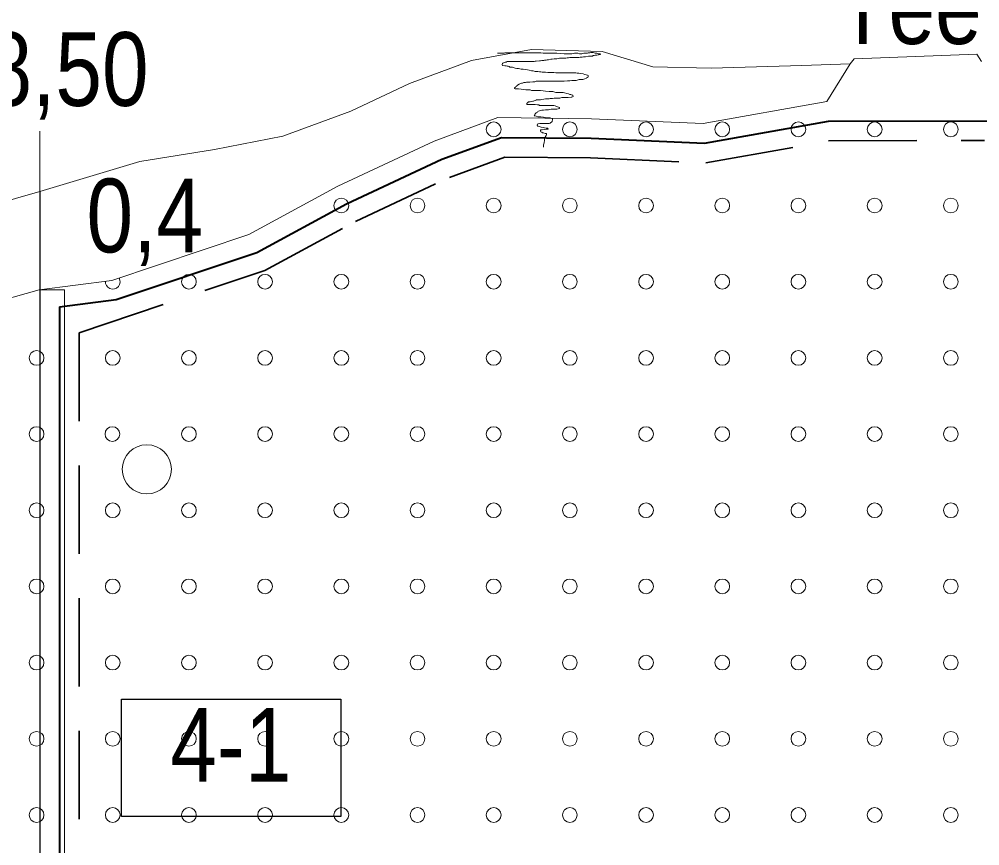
# Model space of a CAD drawing. Extents: x 640121 to 640955, y 6441885 to 6442246.
# Drawn here: x 640648.85 to 640687.94, y 6442170.54 to 6442204.18 of the extents above; entities that cross this region are included whole.
import ezdxf
from ezdxf.enums import TextEntityAlignment as Align

# ---------------------------------------------------------------- set-up
doc = ezdxf.new("R2010")
doc.units = 0
doc.header["$LTSCALE"] = 1.2
doc.linetypes.add('MEDIUM_DASHED', pattern=[4.5, 3, -1.5])
for name, color, linetype, lineweight in [('31', 7, 'Continuous', 13), ('32', 7, 'Continuous', 13), ('33', 7, 'Continuous', 13), ('35', 7, 'Continuous', 35), ('40', 7, 'Continuous', 13), ('43', 7, 'Continuous', 13), ('47', 7, 'Continuous', 13)]:
    doc.layers.add(name, color=color, linetype=linetype, lineweight=lineweight)

msp = doc.modelspace()

# ---------------------------------------------------------------- linework, layer by layer
at = {"layer": '31'}
for points in [[(640635.03, 6442189.74), (640635.65, 6442190.39), (640637.35, 6442192.02), (640639.06, 6442193.19), (640642.55, 6442194.82), (640644.42, 6442195.55), (640646.61, 6442196.28), (640649.69, 6442197.16), (640653.76, 6442198.39), (640656.8, 6442198.87), (640659.58, 6442199.42), (640662.34, 6442200.43), (640664.73, 6442201.56), (640667.25, 6442202.5), (640669.69, 6442202.94), (640672.57, 6442202.86), (640674.63, 6442202.24), (640677.01, 6442202.19), (640680.69, 6442202.29), (640682.66, 6442202.36), (640682.82, 6442202.57), (640687.82, 6442202.76), (640688.01, 6442202.46)], [(640635.03, 6442184.5), (640638.16, 6442187.48), (640641.08, 6442189.5), (640643.27, 6442190.84), (640646.48, 6442192.27), (640649.66, 6442193.16), (640652.62, 6442193.55), (640658.2, 6442195.42), (640661.81, 6442197.38), (640665.74, 6442199.21), (640668.33, 6442200.18), (640672.14, 6442200.13), (640676.68, 6442199.93), (640681.71, 6442200.83), (640682.66, 6442202.36)]]:
    msp.add_lwpolyline(points, dxfattribs=at)
at = {"layer": '32', "lineweight": 25}
msp.add_line((640649.69, 6442197.16), (640649.69, 6442075.16), dxfattribs=at)
at = {"layer": '33'}
msp.add_lwpolyline([(640650.69, 6442157.16), (640650.69, 6442193.16), (640649.69, 6442193.16), (640649.69, 6442193.16), (640649.69, 6442157.16)], close=True, dxfattribs=at)
at = {"layer": '33', "lineweight": 25}
msp.add_lwpolyline([(640653.02, 6442176.51), (640661.94, 6442176.51), (640661.94, 6442171.73), (640653.02, 6442171.73)], close=True, dxfattribs=at)
at = {"layer": '35', "lineweight": 40}
for p, q in [((640681.78, 6442200.03), (640688.53, 6442200.04)), ((640650.49, 6442192.47), (640650.49, 6442078.2))]:
    msp.add_line(p, q, dxfattribs=at)
at = {"layer": '35', "lineweight": 13}
msp.add_line((640649.69, 6442197.16), (640649.69, 6442199.62), dxfattribs=at)
at = {"layer": '35', "linetype": 'MEDIUM_DASHED'}
for p, q in [((640681.78, 6442199.23), (640688.13, 6442199.24)), ((640651.29, 6442191.42), (640651.29, 6442127.97))]:
    msp.add_line(p, q, dxfattribs=at)
at = {"layer": '35', "lineweight": 40}
msp.add_lwpolyline([(640650.49, 6442192.47), (640652.8, 6442192.77), (640658.52, 6442194.69), (640662.17, 6442196.67), (640666.05, 6442198.48), (640668.47, 6442199.37), (640672.12, 6442199.33), (640676.73, 6442199.13), (640681.78, 6442200.03)], dxfattribs=at)
at = {"layer": '35', "linetype": 'MEDIUM_DASHED'}
msp.add_lwpolyline([(640651.29, 6442191.42), (640658.84, 6442193.95), (640662.53, 6442195.95), (640666.36, 6442197.74), (640668.61, 6442198.57), (640672.1, 6442198.54), (640676.79, 6442198.33), (640681.92, 6442199.24)], dxfattribs=at)
at = {"layer": '40'}
for points in [[(640668.31, 6442202.8), (640668.37, 6442202.8), (640668.47, 6442202.8), (640668.58, 6442202.8), (640668.61, 6442202.81), (640668.71, 6442202.81), (640668.87, 6442202.81), (640669.19, 6442202.81), (640669.37, 6442202.81), (640669.41, 6442202.81), (640669.45, 6442202.81), (640669.52, 6442202.81), (640669.6, 6442202.81), (640669.71, 6442202.81), (640669.79, 6442202.81), (640669.85, 6442202.81), (640669.94, 6442202.81), (640670.01, 6442202.81), (640670.08, 6442202.81), (640670.17, 6442202.8), (640670.21, 6442202.8), (640670.29, 6442202.8), (640670.38, 6442202.8), (640670.72, 6442202.79), (640671.03, 6442202.77), (640671.13, 6442202.77), (640671.19, 6442202.77), (640671.22, 6442202.77), (640671.27, 6442202.77), (640671.34, 6442202.77), (640671.44, 6442202.79), (640671.49, 6442202.79), (640671.52, 6442202.79), (640671.55, 6442202.79), (640671.58, 6442202.79), (640671.65, 6442202.77), (640671.69, 6442202.77), (640671.74, 6442202.77), (640671.83, 6442202.79), (640671.89, 6442202.79), (640671.97, 6442202.8), (640672, 6442202.81), (640672.07, 6442202.81), (640672.11, 6442202.82), (640672.16, 6442202.82), (640672.21, 6442202.82), (640672.24, 6442202.81), (640672.28, 6442202.8), (640672.33, 6442202.79), (640672.36, 6442202.79)], [(640672.36, 6442202.79), (640672.41, 6442202.77), (640672.45, 6442202.77), (640672.49, 6442202.77), (640672.52, 6442202.75), (640672.49, 6442202.74), (640672.51, 6442202.75), (640672.47, 6442202.74), (640672.42, 6442202.73), (640672.36, 6442202.71), (640672.33, 6442202.71), (640672.28, 6442202.71), (640672.24, 6442202.7), (640672.21, 6442202.7), (640672.18, 6442202.68), (640672.12, 6442202.68), (640672.05, 6442202.67), (640672.01, 6442202.67), (640671.89, 6442202.65), (640671.85, 6442202.64), (640671.81, 6442202.64), (640671.76, 6442202.63), (640671.71, 6442202.63), (640671.68, 6442202.63), (640671.62, 6442202.62), (640671.58, 6442202.62), (640671.47, 6442202.62), (640671.41, 6442202.62), (640671.34, 6442202.62), (640671.26, 6442202.62), (640671.2, 6442202.61), (640671.15, 6442202.61), (640671.09, 6442202.59), (640671.03, 6442202.59), (640670.86, 6442202.59), (640670.83, 6442202.59), (640670.79, 6442202.58), (640670.72, 6442202.57), (640670.62, 6442202.56), (640670.54, 6442202.55), (640670.48, 6442202.55), (640670.39, 6442202.53), (640670.33, 6442202.53), (640670.29, 6442202.51), (640670.23, 6442202.51), (640670.2, 6442202.5), (640670.17, 6442202.5), (640670.11, 6442202.5), (640670.06, 6442202.49), (640670.02, 6442202.49), (640669.89, 6442202.47), (640669.84, 6442202.47)], [(640669.84, 6442202.47), (640669.81, 6442202.46), (640669.75, 6442202.46), (640669.71, 6442202.45), (640669.67, 6442202.45), (640669.64, 6442202.45), (640669.59, 6442202.45), (640669.54, 6442202.45), (640669.49, 6442202.45), (640669.42, 6442202.45), (640669.39, 6442202.45), (640669.33, 6442202.46), (640669.29, 6442202.46), (640669.25, 6442202.46), (640669.22, 6442202.46), (640669.17, 6442202.46), (640669.12, 6442202.46), (640669.05, 6442202.46), (640669.01, 6442202.46), (640668.98, 6442202.46), (640668.92, 6442202.46), (640668.88, 6442202.46), (640668.83, 6442202.46), (640668.8, 6442202.46), (640668.75, 6442202.46), (640668.7, 6442202.45), (640668.67, 6442202.43), (640668.62, 6442202.43), (640668.58, 6442202.41), (640668.56, 6442202.4), (640668.53, 6442202.39), (640668.51, 6442202.37), (640668.5, 6442202.33), (640668.51, 6442202.29), (640668.61, 6442202.28), (640668.67, 6442202.28), (640668.7, 6442202.26), (640668.75, 6442202.26), (640668.79, 6442202.25), (640668.81, 6442202.23), (640668.87, 6442202.23), (640668.92, 6442202.22), (640668.95, 6442202.21), (640669.03, 6442202.19), (640669.1, 6442202.17), (640669.17, 6442202.17), (640669.22, 6442202.16), (640669.27, 6442202.15), (640669.35, 6442202.14), (640669.46, 6442202.13)], [(640669.46, 6442202.13), (640669.6, 6442202.1), (640669.7, 6442202.08), (640669.76, 6442202.07), (640669.85, 6442202.05), (640669.95, 6442202.05), (640670.02, 6442202.04), (640670.08, 6442202.04), (640670.13, 6442202.02), (640670.21, 6442202.02), (640670.27, 6442202.02), (640670.36, 6442202.01), (640670.44, 6442202.01), (640670.51, 6442202.01), (640670.61, 6442202.01), (640670.69, 6442201.99), (640670.75, 6442201.99), (640670.79, 6442201.99), (640670.86, 6442201.99), (640670.93, 6442201.99), (640671.02, 6442201.99), (640671.11, 6442201.99), (640671.2, 6442201.99), (640671.26, 6442201.99), (640671.34, 6442201.99), (640671.38, 6442201.99), (640671.44, 6442201.99), (640671.5, 6442201.99), (640671.56, 6442201.98), (640671.62, 6442201.98), (640671.67, 6442201.97), (640671.8, 6442201.96), (640671.86, 6442201.93), (640671.92, 6442201.91), (640671.97, 6442201.9), (640672, 6442201.89), (640672, 6442201.85), (640671.99, 6442201.81), (640671.97, 6442201.8), (640671.94, 6442201.79), (640671.92, 6442201.77), (640671.87, 6442201.75), (640671.79, 6442201.73), (640671.64, 6442201.72), (640671.51, 6442201.69), (640671.44, 6442201.68), (640671.34, 6442201.68), (640671.26, 6442201.67), (640671.16, 6442201.67), (640671.03, 6442201.66), (640670.84, 6442201.66), (640670.67, 6442201.66)], [(640670.67, 6442201.66), (640670.59, 6442201.66), (640670.51, 6442201.66), (640670.43, 6442201.66), (640670.37, 6442201.66), (640670.31, 6442201.66), (640670.23, 6442201.66), (640670.14, 6442201.65), (640669.96, 6442201.65), (640669.88, 6442201.65), (640669.83, 6442201.63), (640669.75, 6442201.63), (640669.63, 6442201.61), (640669.49, 6442201.61), (640669.45, 6442201.6), (640669.39, 6442201.6), (640669.36, 6442201.59), (640669.33, 6442201.57), (640669.29, 6442201.57), (640669.25, 6442201.56), (640669.22, 6442201.55), (640669.19, 6442201.53), (640669.13, 6442201.49), (640669.1, 6442201.47), (640669.09, 6442201.44), (640669.05, 6442201.43), (640669.04, 6442201.41), (640669.01, 6442201.38), (640669, 6442201.36), (640669.03, 6442201.35), (640669.06, 6442201.35), (640669.12, 6442201.35), (640669.17, 6442201.35), (640669.28, 6442201.33), (640669.36, 6442201.32), (640669.46, 6442201.31), (640669.58, 6442201.3), (640669.64, 6442201.3), (640669.7, 6442201.27), (640669.76, 6442201.27), (640669.93, 6442201.27), (640670.06, 6442201.27), (640670.17, 6442201.26), (640670.27, 6442201.25), (640670.42, 6442201.24), (640670.56, 6442201.24), (640670.68, 6442201.2), (640670.77, 6442201.2), (640670.86, 6442201.2), (640670.95, 6442201.19)], [(640670.95, 6442201.19), (640670.99, 6442201.19), (640671.04, 6442201.18), (640671.13, 6442201.15), (640671.2, 6442201.14), (640671.25, 6442201.12), (640671.29, 6442201.11), (640671.35, 6442201.09), (640671.38, 6442201.08), (640671.39, 6442201.03), (640671.37, 6442201.02), (640671.34, 6442201.01), (640671.31, 6442201), (640671.19, 6442200.99), (640671.13, 6442200.99), (640671.09, 6442200.99), (640671.02, 6442200.99), (640670.93, 6442200.99), (640670.85, 6442200.97), (640670.8, 6442200.97), (640670.75, 6442200.97), (640670.62, 6442200.97), (640670.55, 6442200.95), (640670.51, 6442200.95), (640670.45, 6442200.95), (640670.42, 6442200.94), (640670.36, 6442200.94), (640670.27, 6442200.94), (640670.2, 6442200.93), (640670.12, 6442200.91), (640670.06, 6442200.9), (640670.02, 6442200.9), (640669.97, 6442200.9), (640669.94, 6442200.89), (640669.88, 6442200.89), (640669.87, 6442200.87), (640669.81, 6442200.85), (640669.78, 6442200.84), (640669.75, 6442200.84), (640669.7, 6442200.83), (640669.64, 6442200.82), (640669.58, 6442200.81), (640669.53, 6442200.78), (640669.51, 6442200.76), (640669.51, 6442200.71), (640669.54, 6442200.71), (640669.61, 6442200.71), (640669.71, 6442200.7), (640669.79, 6442200.7), (640669.84, 6442200.7), (640669.94, 6442200.69), (640670, 6442200.69)], [(640670, 6442200.69), (640670.02, 6442200.67), (640670.06, 6442200.67), (640670.12, 6442200.67), (640670.19, 6442200.67), (640670.23, 6442200.67), (640670.33, 6442200.66), (640670.42, 6442200.66), (640670.45, 6442200.66), (640670.5, 6442200.66), (640670.54, 6442200.66), (640670.6, 6442200.66), (640670.66, 6442200.65), (640670.71, 6442200.63), (640670.75, 6442200.61), (640670.8, 6442200.6), (640670.84, 6442200.59), (640670.84, 6442200.54), (640670.72, 6442200.52), (640670.56, 6442200.51), (640670.5, 6442200.51), (640670.39, 6442200.49), (640670.33, 6442200.49), (640670.26, 6442200.49), (640670.19, 6442200.48), (640670.12, 6442200.48), (640670.05, 6442200.46), (640669.96, 6442200.42), (640669.94, 6442200.4), (640669.89, 6442200.37), (640669.87, 6442200.35), (640669.84, 6442200.33), (640669.83, 6442200.29), (640669.81, 6442200.25), (640669.83, 6442200.24), (640669.88, 6442200.23), (640669.95, 6442200.21), (640670.08, 6442200.21), (640670.19, 6442200.19), (640670.25, 6442200.18), (640670.3, 6442200.17), (640670.37, 6442200.17), (640670.45, 6442200.16), (640670.55, 6442200.12), (640670.55, 6442200.07), (640670.54, 6442200.04), (640670.53, 6442200.01), (640670.45, 6442199.95), (640670.42, 6442199.94), (640670.36, 6442199.94), (640670.27, 6442199.94), (640670.19, 6442199.94), (640670.12, 6442199.94), (640670.03, 6442199.94), (640669.95, 6442199.92), (640669.94, 6442199.88), (640669.93, 6442199.86), (640669.94, 6442199.83), (640669.97, 6442199.82), (640670.09, 6442199.79), (640670.18, 6442199.77), (640670.23, 6442199.76), (640670.29, 6442199.75), (640670.35, 6442199.74), (640670.38, 6442199.71), (640670.36, 6442199.7), (640670.3, 6442199.7), (640670.23, 6442199.69), (640670.13, 6442199.68), (640670.09, 6442199.68), (640670.06, 6442199.67), (640670.06, 6442199.62), (640670.08, 6442199.59), (640670.11, 6442199.58), (640670.14, 6442199.56), (640670.19, 6442199.55), (640670.25, 6442199.53), (640670.3, 6442199.52), (640670.31, 6442199.47), (640670.29, 6442199.45), (640670.27, 6442199.41), (640670.25, 6442199.38), (640670.23, 6442199.35), (640670.23, 6442199.31), (640670.23, 6442199.26), (640670.23, 6442199.22), (640670.21, 6442199.19), (640670.21, 6442199.14), (640670.2, 6442199.11), (640670.19, 6442199.07), (640670.18, 6442199.03), (640670.18, 6442198.98), (640670.18, 6442198.97), (640670.18, 6442199.01)]]:
    msp.add_lwpolyline(points, dxfattribs=at)
at = {"layer": '43'}
for centre in [(640668.157, 6442199.695), (640671.257, 6442199.695), (640674.357, 6442199.695), (640677.457, 6442199.695), (640680.557, 6442199.695), (640683.657, 6442199.695), (640686.757, 6442199.695), (640661.957, 6442196.595), (640665.057, 6442196.595), (640668.157, 6442196.595), (640671.257, 6442196.595), (640674.357, 6442196.595), (640677.457, 6442196.595), (640680.557, 6442196.595), (640683.657, 6442196.595), (640686.757, 6442196.595), (640655.757, 6442193.495), (640658.857, 6442193.495), (640661.957, 6442193.495), (640665.057, 6442193.495), (640668.157, 6442193.495), (640671.257, 6442193.495), (640674.357, 6442193.495), (640677.457, 6442193.495), (640680.557, 6442193.495), (640683.657, 6442193.495), (640686.757, 6442193.495), (640649.557, 6442190.395), (640652.657, 6442190.395), (640655.757, 6442190.395), (640658.857, 6442190.395), (640661.957, 6442190.395), (640665.057, 6442190.395), (640668.157, 6442190.395), (640671.257, 6442190.395), (640674.357, 6442190.395), (640677.457, 6442190.395), (640680.557, 6442190.395), (640683.657, 6442190.395), (640686.757, 6442190.395), (640649.557, 6442187.295), (640652.643, 6442187.295), (640655.757, 6442187.295), (640658.857, 6442187.295), (640661.957, 6442187.295), (640665.057, 6442187.295), (640668.157, 6442187.295), (640671.257, 6442187.295), (640674.357, 6442187.295), (640677.457, 6442187.295), (640680.557, 6442187.295), (640683.657, 6442187.295), (640686.757, 6442187.295), (640649.557, 6442184.195), (640652.657, 6442184.195), (640655.757, 6442184.195), (640658.857, 6442184.195), (640661.957, 6442184.195), (640665.057, 6442184.195), (640668.157, 6442184.195), (640671.257, 6442184.195), (640674.357, 6442184.195), (640677.457, 6442184.195), (640680.557, 6442184.195), (640683.657, 6442184.195), (640686.757, 6442184.195), (640649.557, 6442181.095), (640652.657, 6442181.095), (640655.757, 6442181.095), (640658.857, 6442181.095), (640661.957, 6442181.095), (640665.057, 6442181.095), (640668.157, 6442181.095), (640671.257, 6442181.095), (640674.357, 6442181.095), (640677.457, 6442181.095), (640680.557, 6442181.095), (640683.657, 6442181.095), (640686.757, 6442181.095), (640649.557, 6442177.995), (640652.657, 6442177.995), (640655.757, 6442177.995), (640658.857, 6442177.995), (640661.957, 6442177.995), (640665.057, 6442177.995), (640668.157, 6442177.995), (640671.257, 6442177.995), (640674.357, 6442177.995), (640677.457, 6442177.995), (640680.557, 6442177.995), (640683.657, 6442177.995), (640686.757, 6442177.995), (640649.557, 6442174.895), (640652.657, 6442174.895), (640655.757, 6442174.895), (640658.857, 6442174.895), (640661.957, 6442174.895), (640665.057, 6442174.895), (640668.157, 6442174.895), (640671.257, 6442174.895), (640674.357, 6442174.895), (640677.457, 6442174.895), (640680.557, 6442174.895), (640683.657, 6442174.895), (640686.757, 6442174.895), (640649.557, 6442171.795), (640652.657, 6442171.795), (640655.757, 6442171.795), (640658.857, 6442171.795), (640661.957, 6442171.795), (640665.057, 6442171.795), (640668.157, 6442171.795), (640671.257, 6442171.795), (640674.357, 6442171.795), (640677.457, 6442171.795), (640680.557, 6442171.795), (640683.657, 6442171.795), (640686.757, 6442171.795)]:
    msp.add_circle(centre, 0.3, dxfattribs=at)
msp.add_arc((640652.657, 6442193.495), 0.3, 175.2636, 31.5756, dxfattribs=at)
at = {"layer": '47'}
msp.add_circle((640654.042, 6442185.861), 1, dxfattribs=at)

# ---------------------------------------------------------------- texts
at = {"layer": '31', "width": 0.85}
msp.add_text('Tee', height=3, dxfattribs=at).set_placement((640685.075, 6442203.17), align=Align.CENTER)
at = {"layer": '32', "width": 0.85}
for s, p in [('68,50', (640649.85, 6442200.65)), ('0,4', (640653.96, 6442194.69))]:
    msp.add_text(s, height=3, dxfattribs=at).set_placement(p, align=Align.CENTER)
at = {"layer": '33', "width": 0.85}
msp.add_text('4-1', height=3, dxfattribs=at).set_placement((640657.465, 6442173.15), align=Align.CENTER)

doc.saveas('drawing.dxf')
